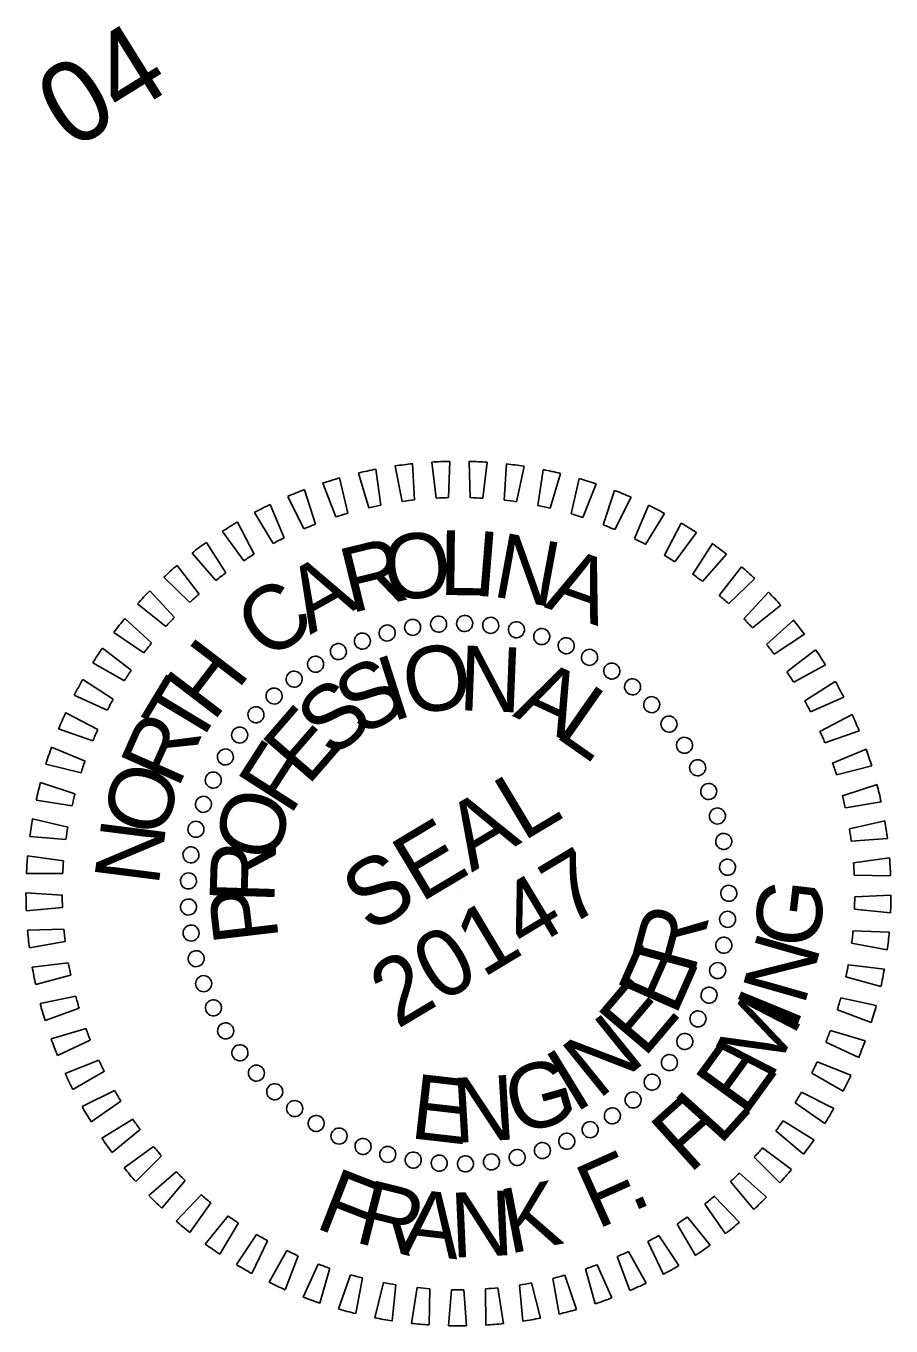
# Model space of a CAD drawing. Extents: x 2045918 to 2047994, y 757573 to 759227.
# Drawn here: x 2047189.9 to 2047269.9, y 759106.8 to 759227.1 of the extents above; entities that cross this region are included whole.
import ezdxf

# ---------------------------------------------------------------- set-up
doc = ezdxf.new("R2010")
doc.units = 0
doc.layers.add('Sheet Data Field CELL', color=7, linetype='Continuous')
doc.layers.add('Sheet PE Seal Cell', color=7, linetype='Continuous')

msp = doc.modelspace()

# ---------------------------------------------------------------- linework, layer by layer
at = {"layer": 'Sheet PE Seal Cell'}
for p, q in [((2047227.43, 759186.76), (2047227.82, 759183.43)), ((2047228.97, 759183.48), (2047229.08, 759186.83)), ((2047230.87, 759186.82), (2047230.97, 759183.47)), ((2047232.12, 759183.42), (2047232.52, 759186.75)), ((2047220.63, 759185.75), (2047221.58, 759182.53)), ((2047222.7, 759182.78), (2047222.24, 759186.1)), ((2047224.01, 759186.4), (2047224.68, 759183.12)), ((2047225.82, 759183.26), (2047225.64, 759186.61)), ((2047234.31, 759186.59), (2047234.12, 759183.24)), ((2047235.26, 759183.09), (2047235.94, 759186.37)), ((2047237.71, 759186.06), (2047237.23, 759182.74)), ((2047238.35, 759182.49), (2047239.32, 759185.71)), ((2047217.32, 759184.81), (2047218.54, 759181.69)), ((2047219.64, 759182.03), (2047218.89, 759185.3)), ((2047241.05, 759185.25), (2047240.29, 759181.98)), ((2047241.39, 759181.63), (2047242.62, 759184.75)), ((2047214.1, 759183.59), (2047215.59, 759180.58)), ((2047216.65, 759181.02), (2047215.63, 759184.21)), ((2047244.31, 759184.14), (2047243.27, 759180.95)), ((2047244.33, 759180.52), (2047245.84, 759183.52)), ((2047211, 759182.1), (2047212.74, 759179.23)), ((2047213.76, 759179.75), (2047212.47, 759182.85)), ((2047247.46, 759182.76), (2047246.15, 759179.68)), ((2047247.18, 759179.15), (2047248.93, 759182.01)), ((2047210.99, 759178.25), (2047209.44, 759181.22)), ((2047250.49, 759181.12), (2047248.92, 759178.16)), ((2047208.04, 759180.34), (2047210.02, 759177.64)), ((2047249.89, 759177.54), (2047251.88, 759180.24)), ((2047205.24, 759178.34), (2047207.44, 759175.82)), ((2047208.36, 759176.51), (2047206.56, 759179.33)), ((2047253.36, 759179.22), (2047251.54, 759176.4)), ((2047205.89, 759174.55), (2047203.85, 759177.21)), ((2047252.46, 759175.71), (2047254.67, 759178.23)), ((2047256.06, 759177.08), (2047254, 759174.43)), ((2047202.62, 759176.11), (2047205.04, 759173.78)), ((2047254.85, 759173.66), (2047257.28, 759175.98)), ((2047203.6, 759172.38), (2047201.34, 759174.86)), ((2047258.56, 759174.72), (2047256.28, 759172.26)), ((2047200.2, 759173.66), (2047202.81, 759171.54)), ((2047257.07, 759171.42), (2047259.68, 759173.52)), ((2047201.5, 759170.03), (2047199.03, 759172.3)), ((2047260.85, 759172.15), (2047258.37, 759169.89)), ((2047198.01, 759171.01), (2047200.79, 759169.13)), ((2047259.08, 759168.99), (2047261.87, 759170.85)), ((2047199.61, 759167.5), (2047196.96, 759169.55)), ((2047262.91, 759169.4), (2047260.25, 759167.36)), ((2047196.05, 759168.18), (2047198.98, 759166.54)), ((2047260.88, 759166.4), (2047263.81, 759168.02)), ((2047197.95, 759164.82), (2047195.13, 759166.64)), ((2047264.73, 759166.47), (2047261.9, 759164.67)), ((2047194.34, 759165.19), (2047197.4, 759163.81)), ((2047262.44, 759163.66), (2047265.51, 759165.02)), ((2047196.52, 759162.01), (2047193.55, 759163.58)), ((2047266.29, 759163.41), (2047263.31, 759161.85)), ((2047192.89, 759162.07), (2047196.06, 759160.96)), ((2047263.77, 759160.8), (2047266.94, 759161.89)), ((2047195.34, 759159.09), (2047192.25, 759160.39)), ((2047267.58, 759160.21), (2047264.48, 759158.92)), ((2047191.72, 759158.83), (2047194.97, 759158)), ((2047264.84, 759157.83), (2047268.1, 759158.65)), ((2047194.41, 759156.07), (2047191.22, 759157.11)), ((2047268.59, 759156.92), (2047265.39, 759155.9)), ((2047190.83, 759155.5), (2047194.14, 759154.96)), ((2047265.66, 759154.79), (2047268.97, 759155.32)), ((2047193.75, 759152.99), (2047190.48, 759153.75)), ((2047269.31, 759153.56), (2047266.04, 759152.82)), ((2047190.23, 759152.12), (2047193.58, 759151.85)), ((2047266.21, 759151.68), (2047269.56, 759151.93)), ((2047193.36, 759149.86), (2047190.03, 759150.33)), ((2047269.74, 759150.15), (2047266.42, 759149.69)), ((2047189.92, 759148.69), (2047193.28, 759148.71)), ((2047266.49, 759148.54), (2047269.85, 759148.5)), ((2047193.23, 759146.71), (2047189.88, 759146.9)), ((2047229.88, 759146.84), (2047229.88, 759146.84)), ((2047269.88, 759146.71), (2047266.53, 759146.54)), ((2047189.91, 759145.25), (2047193.25, 759145.56)), ((2047266.5, 759145.39), (2047269.84, 759145.06)), ((2047193.38, 759143.56), (2047190.02, 759143.46)), ((2047269.72, 759143.27), (2047266.37, 759143.39)), ((2047190.2, 759141.82), (2047193.5, 759142.42)), ((2047266.24, 759142.24), (2047269.54, 759141.63)), ((2047193.79, 759140.43), (2047190.46, 759140.04)), ((2047269.27, 759139.86), (2047265.94, 759140.26)), ((2047190.78, 759138.42), (2047194.01, 759139.3)), ((2047265.71, 759139.14), (2047268.95, 759138.24)), ((2047194.48, 759137.36), (2047191.19, 759136.68)), ((2047191.64, 759135.09), (2047194.79, 759136.25)), ((2047268.52, 759136.5), (2047265.24, 759137.19)), ((2047264.92, 759136.08), (2047268.06, 759134.91)), ((2047195.43, 759134.35), (2047192.21, 759133.39)), ((2047267.49, 759133.21), (2047264.28, 759134.18)), ((2047192.8, 759131.85), (2047195.83, 759133.27)), ((2047263.86, 759133.11), (2047266.9, 759131.67)), ((2047196.63, 759131.43), (2047193.5, 759130.2)), ((2047194.22, 759128.72), (2047197.13, 759130.4)), ((2047262.56, 759130.24), (2047265.46, 759128.55)), ((2047266.18, 759130.03), (2047263.06, 759131.27)), ((2047198.07, 759128.63), (2047195.07, 759127.14)), ((2047264.6, 759126.97), (2047261.6, 759128.48)), ((2047195.91, 759125.72), (2047198.66, 759127.64)), ((2047261.01, 759127.49), (2047263.75, 759125.56)), ((2047199.76, 759125.96), (2047196.89, 759124.22)), ((2047262.76, 759124.06), (2047259.91, 759125.82)), ((2047197.85, 759122.88), (2047200.43, 759125.03)), ((2047259.23, 759124.89), (2047261.8, 759122.72)), ((2047201.66, 759123.45), (2047198.96, 759121.46)), ((2047260.68, 759121.32), (2047257.99, 759123.32)), ((2047200.03, 759120.21), (2047202.41, 759122.58)), ((2047257.24, 759122.45), (2047259.61, 759120.07)), ((2047203.78, 759121.11), (2047201.25, 759118.9)), ((2047258.38, 759118.77), (2047255.86, 759120.99)), ((2047202.43, 759117.74), (2047204.6, 759120.3)), ((2047255.04, 759120.19), (2047257.2, 759117.61)), ((2047206.09, 759118.96), (2047203.76, 759116.54)), ((2047205.03, 759115.49), (2047206.97, 759118.23)), ((2047252.66, 759118.12), (2047254.58, 759115.37)), ((2047255.86, 759116.42), (2047253.54, 759118.85)), ((2047208.57, 759117.02), (2047206.46, 759114.41)), ((2047253.15, 759114.3), (2047251.05, 759116.92)), ((2047207.82, 759113.47), (2047209.52, 759116.37)), ((2047250.1, 759116.27), (2047251.79, 759113.37)), ((2047211.21, 759115.3), (2047209.34, 759112.52)), ((2047210.77, 759111.7), (2047212.21, 759114.73)), ((2047247.4, 759114.64), (2047248.83, 759111.61)), ((2047250.26, 759112.42), (2047248.4, 759115.21)), ((2047213.99, 759113.81), (2047212.36, 759110.88)), ((2047213.86, 759110.19), (2047215.04, 759113.33)), ((2047247.23, 759110.79), (2047245.61, 759113.74)), ((2047216.89, 759112.57), (2047215.52, 759109.5)), ((2047217.07, 759108.94), (2047217.97, 759112.18)), ((2047241.63, 759112.12), (2047242.51, 759108.88)), ((2047244.07, 759109.44), (2047242.71, 759112.51)), ((2047244.57, 759113.26), (2047245.73, 759110.11)), ((2047219.88, 759111.58), (2047218.78, 759108.41)), ((2047220.38, 759107.98), (2047221, 759111.28)), ((2047238.6, 759111.24), (2047239.2, 759107.94)), ((2047240.8, 759108.36), (2047239.71, 759111.53)), ((2047222.95, 759110.85), (2047222.13, 759107.6)), ((2047223.75, 759107.31), (2047224.09, 759110.65)), ((2047226.07, 759110.39), (2047225.53, 759107.07)), ((2047227.17, 759106.93), (2047227.22, 759110.28)), ((2047229.22, 759110.19), (2047228.96, 759106.85)), ((2047230.61, 759106.84), (2047230.37, 759110.19)), ((2047232.37, 759110.27), (2047232.4, 759106.92)), ((2047234.05, 759107.05), (2047233.52, 759110.37)), ((2047235.51, 759110.62), (2047235.83, 759107.28)), ((2047237.45, 759107.56), (2047236.64, 759110.82))]:
    msp.add_line(p, q, dxfattribs=at)
for radius, start, end in [(40, 91.1486, 93.5122), (40, 86.2171, 88.5807), (40, 101.0116, 103.3752), (40, 96.0801, 98.4437), (40, 81.2856, 83.6492), (40, 76.3541, 78.7177), (40, 105.9431, 108.3067), (40, 71.4226, 73.7862), (40, 110.8746, 113.2382), (36.65, 96.363, 98.1608), (36.65, 91.4314, 93.2293), (36.65, 86.4999, 88.2978), (36.65, 81.5684, 83.3663), (40, 66.491, 68.8547), (40, 115.8061, 118.1697), (36.65, 106.226, 108.0239), (36.65, 101.2945, 103.0924), (36.65, 76.6369, 78.4348), (36.65, 71.7054, 73.5033), (40, 61.5595, 63.9232), (40, 120.7376, 123.1012), (36.65, 111.1575, 112.9554), (36.65, 66.7739, 68.5718), (40, 56.628, 58.9917), (36.65, 116.089, 117.8869), (36.65, 61.8424, 63.6403), (40, 125.6691, 128.0327), (40, 51.6965, 54.0601), (40, 130.6006, 132.9643), (36.65, 121.0205, 122.8184), (36.65, 56.9109, 58.7088), (40, 46.765, 49.1286), (36.65, 125.952, 127.7499), (36.65, 51.9794, 53.7773), (40, 135.5321, 137.8958), (40, 41.8335, 44.1971), (36.65, 130.8835, 132.6814), (36.65, 47.0479, 48.8458), (40, 140.4637, 142.8273), (36.65, 135.815, 137.6129), (36.65, 42.1164, 43.9143), (40, 36.902, 39.2656), (36.65, 140.7465, 142.5444), (36.65, 37.1849, 38.9828), (40, 145.3952, 147.7588), (40, 31.9705, 34.3341), (36.65, 145.678, 147.4759), (40, 150.3267, 152.6903), (36.65, 32.2534, 34.0513), (40, 27.039, 29.4026), (36.65, 150.6095, 152.4074), (36.65, 27.3219, 29.1197), (40, 155.2582, 157.6218), (40, 22.1075, 24.4711), (36.65, 155.541, 157.3389), (36.65, 22.3903, 24.1882), (40, 160.1897, 162.5533), (40, 17.176, 19.5396), (36.65, 160.4725, 162.2704), (36.65, 17.4588, 19.2567), (40, 165.1212, 167.4848), (40, 12.2445, 14.6081), (36.65, 165.404, 167.2019), (36.65, 12.5273, 14.3252), (40, 170.0527, 172.4163), (40, 7.313, 9.6766), (36.65, 170.3356, 172.1334), (36.65, 7.5958, 9.3937), (40, 174.9842, 177.3478), (36.65, 175.2671, 177.065), (36.65, 2.6643, 4.4622), (40, 2.3815, 4.7451), (40, 179.9157, 182.2793), (36.65, 180.1986, 181.9965), (36.65, 357.7328, 359.5307), (40, 357.45, 359.8136), (40, 184.8472, 187.2108), (36.65, 185.1301, 186.928), (36.65, 352.8013, 354.5992), (40, 352.5184, 354.8821), (40, 189.7787, 192.1423), (36.65, 190.0616, 191.8595), (36.65, 347.8698, 349.6677), (40, 347.5869, 349.9506), (40, 194.7102, 197.0738), (36.65, 194.9931, 196.791), (36.65, 342.9383, 344.7362), (40, 342.6554, 345.019), (36.65, 199.9246, 201.7225), (36.65, 338.0068, 339.8047), (40, 199.6417, 202.0054), (40, 337.7239, 340.0875), (36.65, 204.8561, 206.654), (40, 204.5732, 206.9369), (36.65, 333.0753, 334.8732), (40, 332.7924, 335.156), (36.65, 209.7876, 211.5855), (36.65, 328.1438, 329.9417), (40, 209.5047, 211.8684), (40, 327.8609, 330.2245), (36.65, 214.7191, 216.517), (36.65, 323.2123, 325.0102), (40, 214.4363, 216.7999), (36.65, 219.6506, 221.4485), (36.65, 318.2808, 320.0787), (40, 322.9294, 325.293), (40, 219.3678, 221.7314), (36.65, 224.5821, 226.38), (36.65, 313.3493, 315.1471), (40, 317.9979, 320.3615), (40, 224.2993, 226.6629), (36.65, 229.5136, 231.3115), (36.65, 308.4177, 310.2156), (40, 313.0664, 315.43), (36.65, 234.4451, 236.243), (36.65, 303.4862, 305.2841), (40, 229.2308, 231.5944), (40, 308.1349, 310.4985), (36.65, 239.3766, 241.1745), (36.65, 298.5547, 300.3526), (40, 234.1623, 236.5259), (36.65, 244.3082, 246.1061), (36.65, 293.6232, 295.4211), (40, 303.2034, 305.567), (40, 239.0938, 241.4574), (36.65, 249.2397, 251.0376), (36.65, 288.6917, 290.4896), (40, 298.2719, 300.6355), (36.65, 254.1712, 255.9691), (36.65, 283.7602, 285.5581), (40, 244.0253, 246.3889), (36.65, 259.1027, 260.9006), (36.65, 264.0342, 265.8321), (36.65, 268.9657, 270.7636), (36.65, 273.8972, 275.6951), (36.65, 278.8287, 280.6266), (40, 293.3404, 295.704), (40, 248.9568, 251.3204), (40, 288.4089, 290.7725), (40, 253.8883, 256.2519), (40, 258.8198, 261.1834), (40, 278.5458, 280.9095), (40, 283.4773, 285.841), (40, 263.7513, 266.1149), (40, 268.6828, 271.0464), (40, 273.6143, 275.978)]:
    msp.add_arc((2047229.88, 759146.84), radius, start, end, dxfattribs=at)
for centre, major_axis in [((2047225.64, 759171.47), (-0.177, 0.721)), ((2047228.04, 759171.77), (-0.106, 0.735)), ((2047230.45, 759171.83), (-0.035, 0.742)), ((2047232.86, 759171.66), (0.037, 0.741)), ((2047220.99, 759170.2), (-0.312, 0.674)), ((2047223.28, 759170.95), (-0.245, 0.701)), ((2047235.24, 759171.25), (0.108, 0.734)), ((2047237.58, 759170.62), (0.179, 0.721)), ((2047218.77, 759169.23), (-0.375, 0.64)), ((2047239.84, 759169.77), (0.247, 0.7)), ((2047216.66, 759168.06), (-0.435, 0.601)), ((2047242, 759168.7), (0.314, 0.673)), ((2047214.68, 759166.68), (-0.491, 0.556)), ((2047244.06, 759167.43), (0.377, 0.639)), ((2047245.98, 759165.97), (0.437, 0.6)), ((2047212.83, 759165.12), (-0.543, 0.506)), ((2047247.75, 759164.32), (0.493, 0.555)), ((2047211.15, 759163.39), (-0.589, 0.452)), ((2047249.35, 759162.52), (0.544, 0.505)), ((2047209.64, 759161.51), (-0.63, 0.393)), ((2047208.32, 759159.48), (-0.665, 0.33)), ((2047250.78, 759160.56), (0.59, 0.45)), ((2047252, 759158.48), (0.631, 0.391)), ((2047207.2, 759157.34), (-0.694, 0.264)), ((2047253.02, 759156.29), (0.666, 0.328)), ((2047206.29, 759155.1), (-0.716, 0.196)), ((2047253.83, 759154.02), (0.694, 0.262)), ((2047205.6, 759152.79), (-0.732, 0.126)), ((2047254.41, 759151.67), (0.717, 0.194)), ((2047205.14, 759150.42), (-0.74, 0.055)), ((2047254.76, 759149.28), (0.732, 0.124)), ((2047204.91, 759148.01), (-0.742, -0.017)), ((2047254.88, 759146.87), (0.74, 0.053)), ((2047204.91, 759145.6), (-0.737, -0.088)), ((2047254.77, 759144.46), (0.742, -0.019)), ((2047205.15, 759143.19), (-0.725, -0.159)), ((2047254.42, 759142.06), (0.737, -0.091)), ((2047205.62, 759140.82), (-0.706, -0.228)), ((2047253.85, 759139.72), (0.725, -0.161)), ((2047206.31, 759138.51), (-0.681, -0.296)), ((2047253.05, 759137.44), (0.706, -0.23)), ((2047207.22, 759136.27), (-0.649, -0.36)), ((2047208.35, 759134.14), (-0.612, -0.421)), ((2047252.03, 759135.25), (0.68, -0.297)), ((2047250.81, 759133.16), (0.648, -0.362)), ((2047209.67, 759132.12), (-0.568, -0.478)), ((2047249.39, 759131.21), (0.61, -0.423)), ((2047211.19, 759130.23), (-0.519, -0.53)), ((2047247.79, 759129.4), (0.567, -0.479)), ((2047212.88, 759128.51), (-0.466, -0.578)), ((2047214.73, 759126.95), (-0.408, -0.62)), ((2047246.03, 759127.75), (0.518, -0.532)), ((2047244.11, 759126.28), (0.464, -0.579)), ((2047216.72, 759125.58), (-0.346, -0.657)), ((2047242.06, 759125), (0.406, -0.622)), ((2047218.83, 759124.41), (-0.281, -0.687)), ((2047221.05, 759123.45), (-0.213, -0.711)), ((2047239.89, 759123.93), (0.344, -0.658)), ((2047223.34, 759122.71), (-0.144, -0.728)), ((2047225.7, 759122.19), (-0.073, -0.739)), ((2047235.31, 759122.43), (0.211, -0.712)), ((2047237.64, 759123.07), (0.279, -0.688)), ((2047228.1, 759121.9), (-0.001, -0.742)), ((2047230.52, 759121.84), (0.071, -0.739)), ((2047232.93, 759122.02), (0.142, -0.729))]:
    msp.add_ellipse(centre, major_axis=major_axis, ratio=0.999708, dxfattribs=at)

# ---------------------------------------------------------------- texts
at = {"layer": 'Sheet Data Field CELL'}
msp.add_text('04', height=7.5, rotation=31.918, dxfattribs=at).set_placement((2047194.07, 759215.51))
at = {"layer": 'Sheet PE Seal Cell'}
for s, height, rotation, p in [('R', 6, 13.8401, (2047219.88, 759172.75)), ('O', 6, 6.5508, (2047223.27, 759173.85)), ('L', 6, 359.3506, (2047228.08, 759174.47)), ('I', 6, 355.3629, (2047231.15, 759174.44)), ('N', 6, 349.5264, (2047232.88, 759174.37)), ('A', 6, 340.5961, (2047237.75, 759173.35)), ('A', 6, 29.3273, (2047216.15, 759170.76)), ('C', 6, 38.2117, (2047212.38, 759168.18)), ('H', 6, 52.5806, (2047207.19, 759162.63)), ('O', 6, 9.375, (2047225.26, 759163.3)), ('I', 6, 17.7649, (2047223.69, 759162.7)), ('N', 6, 357.6615, (2047229.84, 759163.82)), ('S', 6, 31.9248, (2047220.95, 759161.25)), ('A', 6, 335.1412, (2047234.81, 759163.28)), ('T', 6, 58.9737, (2047205.56, 759159.98)), ('S', 6, 40.305, (2047218.21, 759159.22)), ('L', 6, 325.0081, (2047238.64, 759161.46)), ('E', 6, 49.1041, (2047215.94, 759156.71)), ('R', 6, 66.0707, (2047203.93, 759156.45)), ('F', 6, 57.3313, (2047214.29, 759153.95)), ('O', 6, 73.7333, (2047202.57, 759151.82)), ('SEAL', 6.184, 30.9194, (2047221.64, 759143.11)), ('O', 6, 76.279, (2047213.06, 759149.56)), ('N', 6, 82.753, (2047202.13, 759147.44)), ('R', 6, 88.2053, (2047212.84, 759145.86)), ('20147', 6.185, 30.9194, (2047224.22, 759134.26)), ('P', 6, 96.7125, (2047213.28, 759142.61)), ('G', 6, 83.3674, (2047263.11, 759141.64)), ('R', 6, 74.9171, (2047251.63, 759139.16)), ('E', 6, 66.1641, (2047249.95, 759135.41)), ('N', 6, 74.0311, (2047261.84, 759136.35)), ('E', 6, 49.7605, (2047247.05, 759131.54)), ('M', 6, 62.7294, (2047258.71, 759129.39)), ('I', 6, 67.6756, (2047261, 759134.13)), ('N', 6, 38.9112, (2047242.81, 759127.71)), ('E', 6, 54.0871, (2047256.36, 759126.08)), ('G', 6, 15.877, (2047235.21, 759124.47)), ('I', 6, 31.4617, (2047240.62, 759126.47)), ('E', 6, 353.4938, (2047225.28, 759124.23)), ('N', 6, 3.3473, (2047229.49, 759123.77)), ('F', 6, 41.931, (2047251.24, 759120.83)), ('L', 6, 47.9707, (2047254.04, 759123.43)), ('F', 6, 24.1135, (2047242.7, 759115.74)), ('F', 6, 338.6809, (2047216.46, 759115.98)), ('R', 6, 345.8883, (2047220.14, 759114.62)), ('A', 6, 353.3363, (2047224.46, 759113.62)), ('N', 6, 2.576, (2047229.26, 759113.15)), ('K', 6, 10.9504, (2047234.53, 759113.49)), ('.', 6, 22.4779, (2047245.9, 759117.38))]:
    msp.add_text(s, height=height, rotation=rotation, dxfattribs=at).set_placement(p)

doc.saveas('drawing.dxf')
